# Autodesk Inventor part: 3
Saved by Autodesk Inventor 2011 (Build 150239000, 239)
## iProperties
Created: 2012-07
Part Number: 3
Document SubType Name: Modeling
Designer: R.JANSSEN
Mass: 47.3055 g
Surface Area: 110.311 cm^2
Volume: 47.3055 cm^3
Density: 1 g/cm^3
Author: R.JANSSEN
Translation Standard: STEP AP203
FileName: //expscmdclustefs.cadenas.external/client_exchange/iodir/jobs/output/wkb47459197_no0//0//151580_DNG_6_12_PPV_A_2_03.stp
PostProcessor: Build: 239, Release: 2011 RTM - Date: Wed 02/17/2010
Sent Units: millimeter
Uncertainty: 0.0
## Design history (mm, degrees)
feature "Base1"
node "3"
